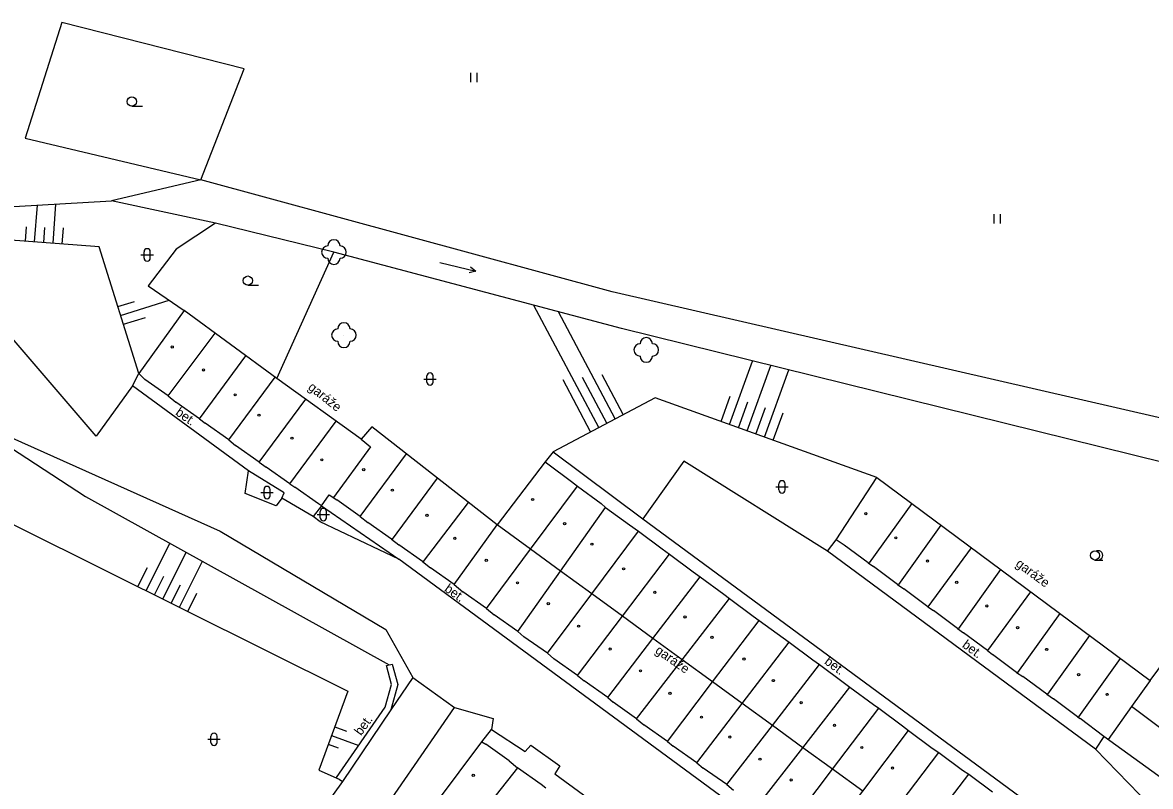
# Model space of a CAD drawing. Extents: x -737488 to -734267, y -1145775 to -1142573.
# Drawn here: x -737046.3 to -736955, y -1144821.8 to -1144760 of the extents above; entities that cross this region are included whole.
import ezdxf

# ---------------------------------------------------------------- set-up
doc = ezdxf.new("R2010")
doc.units = 0
for name, color, linetype in [('Vrstva 1', 7, 'Continuous'), ('Vrstva 10', 7, 'Continuous'), ('Vrstva 11', 7, 'Continuous'), ('Vrstva 12', 7, 'Continuous'), ('Vrstva 14', 7, 'Continuous'), ('Vrstva 3', 7, 'Continuous'), ('Vrstva 4', 7, 'Continuous'), ('Vrstva 5', 7, 'Continuous'), ('Vrstva 8', 7, 'Continuous'), ('Vrstva 9', 7, 'Continuous')]:
    doc.layers.add(name, color=color, linetype=linetype)

# ---------------------------------------------------------------- blocks, each defined once
blk = doc.blocks.new('3.130')
at = {"layer": 'Vrstva 1'}
blk.add_circle((0, 0), 0.001, dxfattribs=at)
for centre, start, end in [((0, 1), 0, 180), ((-1, 0), 90, 270), ((1, 0), 270, 90), ((0, -1), 180, 360)]:
    blk.add_arc(centre, 1, start, end, dxfattribs=at)
blk = doc.blocks.new('3.040')
at = {"layer": 'Vrstva 1'}
blk.add_line((0, -0.75), (1.75, -0.75), dxfattribs=at)
blk.add_circle((0, 0), 0.75, dxfattribs=at)
blk = doc.blocks.new('3.060')
at = {"layer": 'Vrstva 1'}
for p, q in [((-0.5, -0.75), (-0.5, 0.75)), ((0.5, -0.75), (0.5, 0.75))]:
    blk.add_line(p, q, dxfattribs=at)
blk = doc.blocks.new('3.110')
at = {"layer": 'Vrstva 1'}
blk.add_line((0, -0.75), (1.25, -0.75), dxfattribs=at)
blk.add_circle((0, 0), 0.75, dxfattribs=at)
blk.add_arc((0.5, 0), 0.75, 249.4944, 109.0474, dxfattribs=at)
blk = doc.blocks.new('3.160')
at = {"layer": 'Vrstva 1'}
for p, q in [((-1, 0), (1, 0)), ((-0.5, -0.5), (-0.5, 0.5)), ((0.5, -0.5), (0.5, 0.5))]:
    blk.add_line(p, q, dxfattribs=at)
for centre, start, end in [((0, 0.5), 0, 180), ((0, -0.5), 180, 360)]:
    blk.add_arc(centre, 0.5, start, end, dxfattribs=at)
blk = doc.blocks.new('8.021')
at = {"layer": 'Vrstva 1'}
blk.add_line((-3, 0), (3, 0), dxfattribs=at)
blk.add_lwpolyline([(2, 0.5), (3, 0), (2, -0.5)], dxfattribs=at)
blk = doc.blocks.new('4.020')
at = {"layer": 'Vrstva 1'}
blk.add_circle((0, 0), 0.175, dxfattribs=at)

msp = doc.modelspace()

# ---------------------------------------------------------------- linework, layer by layer
at = {"layer": 'Vrstva 10'}
for points in [[(-737031.9, -1144772.69), (-737039.14, -1144774.39)], [(-736890.44, -1144798.42), (-736923.05, -1144800.51), (-736950.66, -1144792.79), (-736998.6, -1144781.74), (-737031.9, -1144772.69)], [(-737030.73, -1144776.19), (-737039.14, -1144774.39)], [(-736889.19, -1144801.99), (-736923.55, -1144803.95), (-736953.91, -1144795.59), (-736997.86, -1144784.72), (-737021.13, -1144778.53)], [(-737037.44, -1144789.35), (-737040.37, -1144793.43), (-737050.27, -1144781.9), (-737054.84, -1144786.68), (-737064.24, -1144782.12)], [(-737037.44, -1144789.35), (-737036.93, -1144788.35)], [(-737028.04, -1144796.23), (-737037.44, -1144789.35)], [(-737051.38, -1144791.69), (-737030.33, -1144801.12)], [(-737003.38, -1144794.68), (-737004.03, -1144795.51)], [(-737003.38, -1144794.68), (-736996.12, -1144800.1)], [(-737028.32, -1144798.07), (-737028.04, -1144796.23)], [(-737022.82, -1144799.92), (-737025.36, -1144798.43), (-737025.17, -1144798.02), (-737028.04, -1144796.23)], [(-736981.18, -1144802.72), (-736992.81, -1144795.46), (-736996.12, -1144800.1)], [(-737025.36, -1144798.43), (-737025.81, -1144799.05), (-737028.32, -1144798.07)], [(-737022.14, -1144799.06), (-737022.82, -1144799.92)], [(-737022.14, -1144799.06), (-737015.87, -1144803.38)], [(-737015.87, -1144803.38), (-737022.24, -1144800.36), (-737022.82, -1144799.92)], [(-736996.12, -1144800.1), (-736957.11, -1144828.85)], [(-737030.33, -1144801.12), (-737016.94, -1144809.06), (-737014.75, -1144812.96)], [(-736981.18, -1144802.72), (-736980.47, -1144801.8)], [(-736985.01, -1144826.08), (-737015.87, -1144803.38)], [(-736959.5, -1144818.74), (-736981.18, -1144802.72)], [(-737020.93, -1144821.04), (-737016.99, -1144815.36), (-737016.48, -1144813.53), (-737016.89, -1144811.99), (-737016.41, -1144811.86), (-737015.96, -1144813.53), (-737016.53, -1144815.58)], [(-737014.75, -1144812.96), (-737016.53, -1144815.58)], [(-737014.75, -1144812.96), (-737011.37, -1144815.38)], [(-737017.47, -1144829.86), (-737018.62, -1144828.91), (-737018.64, -1144825.89), (-737011.37, -1144815.38)], [(-737011.37, -1144815.38), (-737008.25, -1144816.27), (-737008.38, -1144817.17)], [(-737016.53, -1144815.58), (-737020.45, -1144821.37)], [(-737009.16, -1144818.15), (-737008.38, -1144817.17)], [(-737008.38, -1144817.17), (-737005.66, -1144818.93), (-737005.19, -1144818.43), (-737002.85, -1144820.11), (-737003.24, -1144820.75), (-736979.34, -1144838.25), (-736979.49, -1144838.52), (-736974.47, -1144842)], [(-736958.8, -1144817.72), (-736959.5, -1144818.74)], [(-736959.5, -1144818.74), (-736955.04, -1144823.33), (-736953.3, -1144828.18), (-736954.31, -1144833.5), (-736960.23, -1144841.33), (-736960.44, -1144841.7), (-736960.72, -1144842.34), (-736960.93, -1144843.01), (-736961.07, -1144843.69), (-736961.12, -1144844.39), (-736961.09, -1144845.09), (-736960.99, -1144845.78), (-736960.8, -1144846.45), (-736960.54, -1144847.1), (-736960.21, -1144847.72), (-736959.81, -1144848.29), (-736950.65, -1144855.27), (-736945.8, -1144858.5), (-736922.97, -1144874.73), (-736918.01, -1144874.29)], [(-737020.45, -1144821.37), (-737022.83, -1144824.72), (-737022.04, -1144825.31), (-737022.5, -1144826.13)]]:
    msp.add_lwpolyline(points, dxfattribs=at)
at = {"layer": 'Vrstva 12'}
for points in [[(-737050.8, -1144775.07), (-737039.14, -1144774.39)], [(-737045.36, -1144777.71), (-737045.14, -1144774.74)], [(-737043.86, -1144777.82), (-737043.63, -1144774.65)], [(-737046.11, -1144777.65), (-737046.02, -1144776.5)], [(-737044.61, -1144777.76), (-737044.52, -1144776.54)], [(-737043.12, -1144777.88), (-737043.02, -1144776.57)], [(-737036.93, -1144788.35), (-737040.13, -1144778.1), (-737050.51, -1144777.32)], [(-737076.08, -1144778.71), (-737072.38, -1144785.63), (-737059.8, -1144794.25), (-737020.01, -1144814.06), (-737022.36, -1144820.44), (-737020.72, -1144821.18), (-737020.45, -1144821.37)], [(-737038.62, -1144782.94), (-737037.28, -1144782.52)], [(-737038.4, -1144783.65), (-737034.47, -1144782.43)], [(-736999.7, -1144792.73), (-737004.94, -1144782.84)], [(-736998.37, -1144792.03), (-737002.96, -1144783.36)], [(-737038.17, -1144784.37), (-737036.38, -1144783.81)], [(-736989.1, -1144792.48), (-736987.25, -1144787.35)], [(-736987.69, -1144792.99), (-736985.78, -1144787.71)], [(-736986.28, -1144793.5), (-736984.32, -1144788.07)], [(-737000.36, -1144793.08), (-737002.59, -1144788.88)], [(-736999.04, -1144792.38), (-737001, -1144788.67)], [(-736997.71, -1144791.68), (-736999.42, -1144788.46)], [(-736977.18, -1144796.78), (-736995.13, -1144790.31), (-737003.38, -1144794.68)], [(-736989.8, -1144792.23), (-736989.07, -1144790.2)], [(-736988.39, -1144792.74), (-736987.64, -1144790.65)], [(-737051.38, -1144791.69), (-737041.24, -1144798.3), (-737016.65, -1144811.92)], [(-736986.98, -1144793.25), (-736986.21, -1144791.1)], [(-736985.57, -1144793.76), (-736984.78, -1144791.55)], [(-737036.33, -1144805.94), (-737034.41, -1144802.09)], [(-737034.98, -1144806.61), (-737033.09, -1144802.81)], [(-737033.64, -1144807.27), (-737031.78, -1144803.54)], [(-737037, -1144805.6), (-737036.22, -1144804.05)], [(-737035.65, -1144806.27), (-737034.89, -1144804.74)], [(-737034.31, -1144806.94), (-737033.56, -1144805.44)], [(-737032.97, -1144807.61), (-737032.23, -1144806.13)], [(-737021.07, -1144816.94), (-737020.12, -1144817.29)], [(-737021.33, -1144817.65), (-737019.13, -1144818.45)], [(-737021.59, -1144818.35), (-737020.78, -1144818.65)]]:
    msp.add_lwpolyline(points, dxfattribs=at)
at = {"layer": 'Vrstva 4'}
for points in [[(-737033.25, -1144783.26), (-737036.93, -1144788.35)], [(-737025.76, -1144788.75), (-737033.25, -1144783.26)], [(-737036.93, -1144788.35), (-737036.45, -1144788.83)], [(-737034.54, -1144790.17), (-737036.45, -1144788.83)], [(-737004.03, -1144795.51), (-737007.92, -1144800.6), (-737018.06, -1144792.66), (-737018.92, -1144793.68), (-737025.76, -1144788.75)], [(-737034.54, -1144790.17), (-737033.93, -1144790.67)], [(-737032.02, -1144792.01), (-737033.93, -1144790.67)], [(-737032.02, -1144792.01), (-737031.56, -1144792.38)], [(-737029.65, -1144793.72), (-737031.56, -1144792.38)], [(-737029.65, -1144793.72), (-737029.1, -1144794.19)], [(-737027.19, -1144795.53), (-737029.1, -1144794.19)], [(-737027.19, -1144795.53), (-737026.61, -1144795.93)], [(-737024.7, -1144797.27), (-737026.61, -1144795.93)], [(-737004.03, -1144795.51), (-737003.83, -1144795.66)], [(-737001.91, -1144797.08), (-737001.43, -1144797.46)], [(-736980.47, -1144801.8), (-736977.18, -1144796.78)], [(-736977.18, -1144796.78), (-736955.06, -1144813.2), (-736950.63, -1144807.23)], [(-737024.7, -1144797.27), (-737024.3, -1144797.56)], [(-737022.14, -1144799.06), (-737022.39, -1144798.9), (-737024.3, -1144797.56)], [(-737022.14, -1144799.06), (-737021.51, -1144798.16), (-737020.91, -1144798.58)], [(-737019, -1144799.92), (-737020.91, -1144798.58)], [(-736999.51, -1144798.88), (-736999.14, -1144799.19)], [(-737019, -1144799.92), (-737018.39, -1144800.41)], [(-737016.48, -1144801.75), (-737018.39, -1144800.41)], [(-736997.22, -1144800.61), (-736996.48, -1144801.12)], [(-737016.48, -1144801.75), (-737015.88, -1144802.23)], [(-736979.83, -1144802.24), (-736980.47, -1144801.8)], [(-737013.97, -1144803.57), (-737015.88, -1144802.23)], [(-736994.56, -1144802.54), (-736993.98, -1144802.98)], [(-737013.97, -1144803.57), (-737013.31, -1144804.09)], [(-737011.4, -1144805.43), (-737013.31, -1144804.09)], [(-736992.06, -1144804.4), (-736991.5, -1144804.8)], [(-736977.89, -1144803.68), (-736977.45, -1144803.98)], [(-737011.4, -1144805.43), (-737010.7, -1144806.02)], [(-736975.51, -1144805.42), (-736975, -1144805.79)], [(-737008.79, -1144807.36), (-737010.7, -1144806.02)], [(-736989.58, -1144806.22), (-736989.12, -1144806.56)], [(-736973.06, -1144807.23), (-736972.6, -1144807.54)], [(-737008.79, -1144807.36), (-737008.15, -1144807.89)], [(-737006.24, -1144809.23), (-737008.15, -1144807.89)], [(-736987.2, -1144807.98), (-736986.7, -1144808.33)], [(-736970.66, -1144808.98), (-736970.18, -1144809.33)], [(-737006.24, -1144809.23), (-737005.76, -1144809.65)], [(-737003.85, -1144810.99), (-737005.76, -1144809.65)], [(-736984.78, -1144809.75), (-736984.28, -1144810.09)], [(-736968.24, -1144810.77), (-736967.82, -1144811.1)], [(-737003.85, -1144810.99), (-737003.34, -1144811.44)], [(-737001.43, -1144812.78), (-737003.34, -1144811.44)], [(-736982.36, -1144811.51), (-736981.82, -1144811.9)], [(-736965.88, -1144812.54), (-736965.38, -1144812.86)], [(-737001.43, -1144812.78), (-737000.87, -1144813.23)], [(-736998.96, -1144814.57), (-737000.87, -1144813.23)], [(-736979.9, -1144813.32), (-736979.37, -1144813.72)], [(-736998.96, -1144814.57), (-736998.54, -1144814.96)], [(-736963.44, -1144814.3), (-736962.88, -1144814.69)], [(-736996.63, -1144816.3), (-736998.54, -1144814.96)], [(-736977.45, -1144815.14), (-736977.03, -1144815.44)], [(-736996.63, -1144816.3), (-736996.05, -1144816.79)], [(-736960.94, -1144816.13), (-736960.74, -1144816.28)], [(-736994.14, -1144818.13), (-736996.05, -1144816.79)], [(-736975.11, -1144816.86), (-736974.62, -1144817.24)], [(-737016.29, -1144828.09), (-737016.5, -1144827.97), (-737009.16, -1144818.15)], [(-737009.16, -1144818.15), (-737008.85, -1144818.35)], [(-736994.14, -1144818.13), (-736993.67, -1144818.51)], [(-736953.48, -1144821.58), (-736958.8, -1144817.72)], [(-737006.94, -1144819.69), (-737008.85, -1144818.35)], [(-736991.76, -1144819.85), (-736993.67, -1144818.51)], [(-736972.7, -1144818.66), (-736972.17, -1144819.02)], [(-737006.94, -1144819.69), (-737006.26, -1144820.26)], [(-736991.76, -1144819.85), (-736991.25, -1144820.28)], [(-737003.99, -1144821.91), (-737004.35, -1144821.6), (-737006.26, -1144820.26)], [(-736989.34, -1144821.62), (-736991.25, -1144820.28)], [(-736970.25, -1144820.44), (-736969.74, -1144820.77)], [(-736989.34, -1144821.62), (-736988.79, -1144822.06)]]:
    msp.add_lwpolyline(points, dxfattribs=at)
at = {"layer": 'Vrstva 5'}
for points in [[(-737034.54, -1144790.17), (-737030.74, -1144785.1)], [(-737032.02, -1144792.01), (-737028.25, -1144786.92)], [(-737029.65, -1144793.72), (-737025.9, -1144788.65)], [(-737027.19, -1144795.53), (-737023.42, -1144790.44)], [(-737024.7, -1144797.27), (-737020.96, -1144792.21)], [(-737018.92, -1144793.68), (-737018.18, -1144794.29), (-737021.18, -1144798.39)], [(-737019, -1144799.92), (-737015.27, -1144794.85)], [(-737016.4, -1144801.75), (-737012.75, -1144796.82)], [(-737008.79, -1144807.36), (-737005.22, -1144802.56), (-737001.43, -1144797.46)], [(-737013.89, -1144803.57), (-737010.24, -1144798.79)], [(-736974.36, -1144798.87), (-736977.81, -1144803.68)], [(-737006.24, -1144809.23), (-737002.78, -1144804.34), (-736999.14, -1144799.19)], [(-737011.4, -1144805.43), (-737007.92, -1144800.6)], [(-737005.22, -1144802.56), (-737007.92, -1144800.6)], [(-736972, -1144800.63), (-736975.43, -1144805.42)], [(-737003.85, -1144810.99), (-737000.26, -1144806.18), (-736996.48, -1144801.12)], [(-737002.78, -1144804.34), (-737005.22, -1144802.56)], [(-736969.55, -1144802.45), (-736973.06, -1144807.23)], [(-737001.43, -1144812.78), (-736997.78, -1144807.98), (-736993.98, -1144802.98)], [(-737000.26, -1144806.18), (-737002.78, -1144804.34)], [(-736967.17, -1144804.21), (-736970.58, -1144808.98)], [(-736998.96, -1144814.57), (-736995.31, -1144809.79), (-736991.5, -1144804.8)], [(-736997.78, -1144807.98), (-737000.26, -1144806.18)], [(-736964.75, -1144806.01), (-736968.24, -1144810.77)], [(-736996.63, -1144816.3), (-736992.94, -1144811.51), (-736989.12, -1144806.56)], [(-736995.31, -1144809.79), (-736997.78, -1144807.98)], [(-736962.38, -1144807.77), (-736965.8, -1144812.54)], [(-736994.14, -1144818.13), (-736990.48, -1144813.31), (-736986.7, -1144808.33)], [(-736992.94, -1144811.51), (-736995.31, -1144809.79)], [(-736959.96, -1144809.56), (-736963.36, -1144814.3)], [(-736991.76, -1144819.85), (-736988.08, -1144815.05), (-736984.28, -1144810.09)], [(-736990.48, -1144813.31), (-736992.94, -1144811.51)], [(-736957.48, -1144811.41), (-736960.86, -1144816.13)], [(-736989.34, -1144821.62), (-736985.64, -1144816.83), (-736981.82, -1144811.9)], [(-736988.08, -1144815.05), (-736990.48, -1144813.31)], [(-736955.06, -1144813.2), (-736956.57, -1144815.3), (-736958.47, -1144817.96)], [(-736986.88, -1144823.4), (-736983.18, -1144818.63), (-736979.37, -1144813.72)], [(-736985.64, -1144816.83), (-736988.08, -1144815.05)], [(-736984.43, -1144825.19), (-736980.78, -1144820.38), (-736977.03, -1144815.44)], [(-736951.6, -1144819.02), (-736956.57, -1144815.3)], [(-736983.18, -1144818.63), (-736985.64, -1144816.83)], [(-736981.97, -1144826.97), (-736978.33, -1144822.16), (-736974.62, -1144817.24)], [(-736980.78, -1144820.38), (-736983.18, -1144818.63)], [(-736979.55, -1144828.75), (-736975.9, -1144823.93), (-736972.17, -1144819.02)], [(-737006.26, -1144820.26), (-737010.13, -1144825.14), (-737013.86, -1144829.86)], [(-736978.33, -1144822.16), (-736980.78, -1144820.38)], [(-736977.15, -1144830.5), (-736973.49, -1144825.69), (-736969.74, -1144820.77)]]:
    msp.add_lwpolyline(points, dxfattribs=at)
at = {"layer": 'Vrstva 9'}
for points in [[(-737031.9, -1144772.69), (-737028.41, -1144763.71), (-737043.17, -1144759.96), (-737046.12, -1144769.31), (-737031.9, -1144772.69)], [(-737030.73, -1144776.19), (-737033.9, -1144778.29), (-737036.17, -1144781.27), (-737033.25, -1144783.26)], [(-737021.13, -1144778.53), (-737030.73, -1144776.19)], [(-737025.76, -1144788.75), (-737021.13, -1144778.53)], [(-737003.83, -1144795.66), (-737001.91, -1144797.08)], [(-737001.43, -1144797.46), (-736999.51, -1144798.88)], [(-736999.14, -1144799.19), (-736997.22, -1144800.61)], [(-736996.48, -1144801.12), (-736994.56, -1144802.54)], [(-736977.89, -1144803.68), (-736979.83, -1144802.24)], [(-736993.98, -1144802.98), (-736992.06, -1144804.4)], [(-736975.51, -1144805.42), (-736977.45, -1144803.98)], [(-736991.5, -1144804.8), (-736989.58, -1144806.22)], [(-736973.06, -1144807.23), (-736975, -1144805.79)], [(-736989.12, -1144806.56), (-736987.2, -1144807.98)], [(-736970.66, -1144808.98), (-736972.6, -1144807.54)], [(-736986.7, -1144808.33), (-736984.78, -1144809.75)], [(-736968.24, -1144810.77), (-736970.18, -1144809.33)], [(-736984.28, -1144810.09), (-736982.36, -1144811.51)], [(-736965.88, -1144812.54), (-736967.82, -1144811.1)], [(-736981.82, -1144811.9), (-736979.9, -1144813.32)], [(-736963.44, -1144814.3), (-736965.38, -1144812.86)], [(-736979.37, -1144813.72), (-736977.45, -1144815.14)], [(-736977.03, -1144815.44), (-736975.11, -1144816.86)], [(-736960.94, -1144816.13), (-736962.88, -1144814.69)], [(-736958.8, -1144817.72), (-736960.74, -1144816.28)], [(-736974.62, -1144817.24), (-736972.7, -1144818.66)], [(-736972.17, -1144819.02), (-736970.25, -1144820.44)], [(-736969.74, -1144820.77), (-736967.82, -1144822.19)]]:
    msp.add_lwpolyline(points, dxfattribs=at)

# ---------------------------------------------------------------- block references
at = {"layer": 'Vrstva 11', "xscale": 0.5, "yscale": 0.5}
for p in [(-737021.13, -1144778.53), (-737020.32, -1144785.25), (-736995.85, -1144786.45)]:
    msp.add_blockref('3.130', p, dxfattribs=at)
at = {"layer": 'Vrstva 3', "xscale": 0.5, "yscale": 0.5}
for name, p in [('3.060', (-737009.79, -1144764.4)), ('3.040', (-737037.49, -1144766.35)), ('3.060', (-736967.44, -1144775.84)), ('3.160', (-737036.25, -1144778.76)), ('3.040', (-737028.1, -1144780.84)), ('3.160', (-737013.35, -1144788.8)), ('3.160', (-736984.86, -1144797.53)), ('3.160', (-737026.54, -1144797.99)), ('3.160', (-737021.99, -1144799.77)), ('3.110', (-736959.53, -1144803.07)), ('3.160', (-737030.84, -1144817.95))]:
    msp.add_blockref(name, p, dxfattribs=at)
at = {"layer": 'Vrstva 3', "xscale": 0.5000000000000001, "yscale": 0.5, "rotation": -13.64992279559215}
msp.add_blockref('8.021', (-737011.1, -1144779.73), dxfattribs=at)
at = {"layer": 'Vrstva 8', "xscale": 0.5, "yscale": 0.5}
for p in [(-737034.22, -1144786.21), (-737031.69, -1144788.07), (-737029.13, -1144790.08), (-737027.2, -1144791.73), (-737024.53, -1144793.59), (-737022.11, -1144795.34), (-737018.72, -1144796.14), (-737016.4, -1144797.79), (-737005.05, -1144798.55), (-737013.6, -1144799.83), (-736978.08, -1144799.7), (-737002.46, -1144800.51), (-737011.35, -1144801.69), (-736975.65, -1144801.65), (-737000.25, -1144802.16), (-737008.8, -1144803.47), (-736973.09, -1144803.53), (-736997.68, -1144804.16), (-737006.27, -1144805.29), (-736970.72, -1144805.25), (-736995.16, -1144806.06), (-737003.78, -1144806.98), (-736968.28, -1144807.16), (-736992.71, -1144808.05), (-737001.33, -1144808.8), (-736965.79, -1144808.92), (-736990.53, -1144809.7), (-736998.77, -1144810.65), (-736963.44, -1144810.68), (-736987.94, -1144811.46), (-736996.32, -1144812.41), (-736960.85, -1144812.72), (-736985.56, -1144813.2), (-736993.93, -1144814.23), (-736958.54, -1144814.32), (-736983.31, -1144814.99), (-736991.38, -1144816.16), (-736980.61, -1144816.82), (-736989.09, -1144817.77), (-736978.4, -1144818.61), (-736986.65, -1144819.56), (-737009.85, -1144820.87), (-736975.92, -1144820.28), (-736984.12, -1144821.24)]:
    msp.add_blockref('4.020', p, dxfattribs=at)

# ---------------------------------------------------------------- texts
at = {"layer": 'Vrstva 14'}
for s, rotation, p in [('garáže', 321.462, (-737023.29, -1144789.58)), ('bet.', 324.819, (-737034.02, -1144791.65)), ('garáže', 323.514, (-736966.01, -1144803.88)), ('bet.', 324.819, (-737012.25, -1144805.92)), ('bet.', 323.763, (-736970.34, -1144810.45)), ('garáže', 324.911, (-736995.19, -1144810.91)), ('bet.', 323.763, (-736981.49, -1144811.8)), ('bet.', 53.881, (-737018.94, -1144817.7))]:
    msp.add_text(s, height=0.75, rotation=rotation, dxfattribs=at).set_placement(p)

doc.saveas('drawing.dxf')
